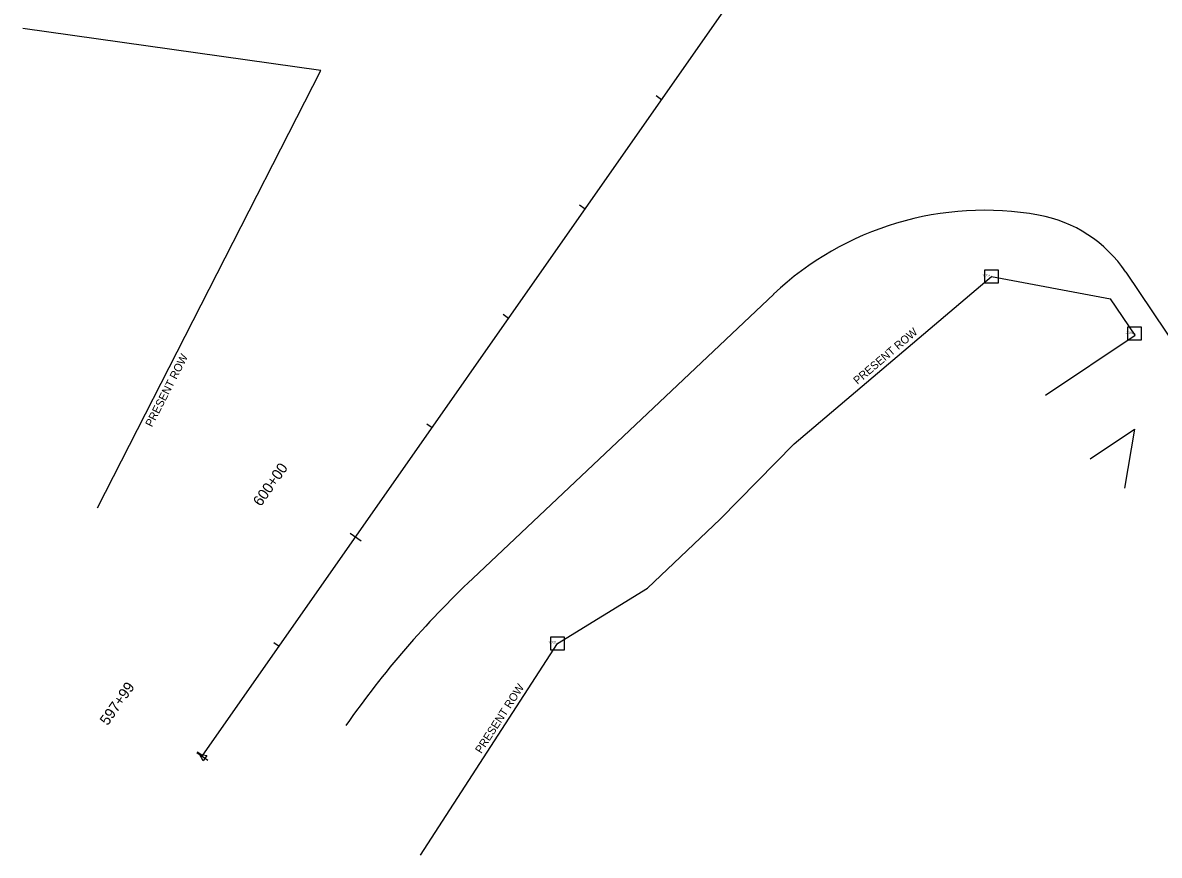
# Model space of a CAD drawing. Extents: x 1790419 to 1799551, y 243603 to 252255.
# Drawn here: x 1795869 to 1796721, y 243603 to 244227 of the extents above; entities that cross this region are included whole.
import ezdxf

# ---------------------------------------------------------------- set-up
doc = ezdxf.new("R2010")
doc.units = 0
for name, color, linetype in [('CL-CNST', 7, 'Continuous'), ('CL-CNSTTXT', 7, 'Continuous'), ('Default', 7, 'Continuous'), ('LS-SURVEY POINT', 7, 'Continuous'), ('Prop_Horiz Alignment', 7, 'Continuous'), ('PRP_ROW', 7, 'Continuous'), ('PRPROWTXT', 7, 'Continuous'), ('Survey BL', 7, 'Continuous')]:
    doc.layers.add(name, color=color, linetype=linetype)

msp = doc.modelspace()

# ---------------------------------------------------------------- linework, layer by layer
at = {"layer": 'CL-CNST'}
for points in [[(1796343.72, 244172.76), (1796347.81, 244169.9)], [(1796286.41, 244090.81), (1796290.51, 244087.95)], [(1796229.1, 244008.86), (1796233.2, 244006)], [(1796171.79, 243926.91), (1796175.89, 243924.05)], [(1796114.48, 243844.96), (1796122.68, 243839.23)], [(1796057.18, 243763.02), (1796061.27, 243760.15)], [(1795999.5, 243680.54), (1796007.7, 243674.81)], [(1795999.5, 243680.54), (1796007.7, 243674.81)], [(1795999.87, 243681.07), (1796003.97, 243678.2)]]:
    msp.add_lwpolyline(points, dxfattribs=at)
at = {"layer": 'Default'}
msp.add_line((1796003.6, 243677.68), (1796959.66, 245044.83), dxfattribs=at)
at = {"layer": 'Prop_Horiz Alignment'}
msp.add_lwpolyline([(1796001.55, 243679.11), (1796007.08, 243678.29), (1796004.21, 243674.19)], close=True, dxfattribs=at)
at = {"layer": 'PRP_ROW'}
for p, q in [((1796092.41, 244191.53), (1795869.06, 244223.09)), ((1795925.08, 243863.78), (1796092.41, 244191.53)), ((1796447.13, 243911.78), (1796595.1, 244037.24)), ((1796595.1, 244037.24), (1796684.21, 244020.54)), ((1796702.69, 243993.2), (1796684.21, 244020.54)), ((1796635.49, 243948.39), (1796702.69, 243993.2)), ((1796669.04, 243900.63), (1796702.26, 243922.78)), ((1796702.26, 243922.78), (1796694.64, 243878.56)), ((1796391.7, 243855.26), (1796447.13, 243911.78)), ((1796337.2, 243803.75), (1796391.7, 243855.26)), ((1796269.83, 243762.18), (1796337.2, 243803.75)), ((1796167.23, 243603.46), (1796269.83, 243762.18))]:
    msp.add_line(p, q, dxfattribs=at)
for points in [[(1796600.1, 244042.24), (1796600.1, 244032.24), (1796590.1, 244032.24), (1796590.1, 244042.24)], [(1796707.31, 243999.45), (1796707.31, 243989.45), (1796697.31, 243989.45), (1796697.31, 243999.45)], [(1796274.83, 243767.18), (1796274.83, 243757.18), (1796264.83, 243757.18), (1796264.83, 243767.18)]]:
    msp.add_lwpolyline(points, close=True, dxfattribs=at)
at = {"layer": 'Survey BL'}
for p, q in [((1796003.6, 243677.68), (1796959.66, 245044.83)), ((1796695.68, 244040.54), (1796735.6, 243981.06)), ((1796206.27, 243810.86), (1796431.8, 244024.01))]:
    msp.add_line(p, q, dxfattribs=at)
for centre, radius, start, end in [((1796589.77, 243856.84), 230, 79.86625, 133.38203), ((1796612.65, 243984.82), 100, 33.86409, 79.86697), ((1796698.2, 243290.34), 716.2, 133.38251, 145.03494)]:
    msp.add_arc(centre, radius, start, end, dxfattribs=at)

# ---------------------------------------------------------------- texts
at = {"layer": 'CL-CNSTTXT'}
for s, p in [('600+00', (1796047.51, 243864.36)), ('597+99', (1795932.71, 243700.19)), ('597+99', (1795932.71, 243700.19))]:
    msp.add_text(s, height=8, rotation=55.0347, dxfattribs=at).set_placement(p)
at = {"layer": 'LS-SURVEY POINT'}
for s, p in [('12204', (1796588.27, 244037.24)), ('+', (1796594.48, 244036.49)), ('12202', (1796695.48, 243994.45)), ('+', (1796701.69, 243993.7)), ('12205', (1796263, 243762.18)), ('+', (1796269.2, 243761.43))]:
    msp.add_text(s, height=1.5, dxfattribs=at).set_placement(p)
at = {"layer": 'PRPROWTXT'}
for rotation, p in [(40.29611, (1796494.62, 243955.98)), (62.95389, (1795965.91, 243923.96)), (57.12053, (1796212.66, 243679.27))]:
    msp.add_text('PRESENT ROW', height=6, rotation=rotation, dxfattribs=at).set_placement(p)

doc.saveas('drawing.dxf')
